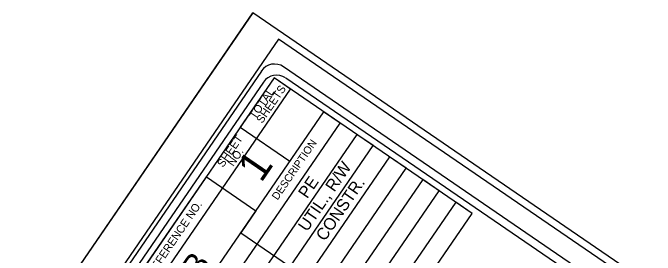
# Model space of a CAD drawing. Extents: x 2312641 to 2338852, y 590461 to 618614.
# Drawn here: x 2324050 to 2329669, y 616493 to 618614 of the extents above; entities that cross this region are included whole.
import ezdxf

# ---------------------------------------------------------------- set-up
doc = ezdxf.new("R2010")
doc.units = 0
for name, color, linetype in [('Exist Other Culture Sign Post Text', 7, 'Continuous'), ('Exist Property Iron Pin Cogo Number', 7, 'Continuous'), ('Exist Utilities Power Joint Use Telephone CELL', 7, 'Continuous'), ('Exist Utilities Power Joint Use Telephone Text', 7, 'Continuous'), ('Exist Vegetation Woods Line Text', 7, 'Continuous')]:
    doc.layers.add(name, color=color, linetype=linetype)

msp = doc.modelspace()

# ---------------------------------------------------------------- linework, layer by layer
at = {"layer": 'Exist Other Culture Sign Post Text'}
msp.add_line((2312821.5, 599166.9), (2326149.2, 618614.2), dxfattribs=at)
at = {"layer": 'Exist Property Iron Pin Cogo Number'}
for points in [[(2338313.5, 609989.2), (2326418.9, 618140.9)], [(2326224.4, 618104.7), (2314510.8, 601013.1)], [(2326242.4, 618007.3), (2315004.1, 601608.8)], [(2324303.9, 614770.3), (2326480.3, 617946.1), (2326336, 618045), (2324159.7, 614869.1)], [(2324456.3, 615302.3), (2325742.6, 617178.9), (2326175.5, 616882.1), (2326043.3, 616689.2), (2327342.5, 615798.9), (2328068.2, 616857.8), (2326336, 618045), (2326039.2, 617611.9), (2326472.3, 617315.3)], [(2336079.9, 611435.1), (2326436.9, 618043.7)], [(2324737.1, 614473.4), (2326913.5, 617649.2), (2326769, 617748.2), (2324592.6, 614572.4)], [(2325025.8, 614275.5), (2327202.1, 617451.4), (2327057.9, 617550.2), (2324881.4, 614374.5)], [(2325314.4, 614077.8), (2327490.8, 617253.6), (2327346.4, 617352.5), (2325170, 614176.7)], [(2325603.2, 613879.8), (2327779.7, 617055.6), (2327635.3, 617154.5), (2325458.9, 613978.9)], [(2325891.8, 613682.1), (2328068.2, 616857.8), (2327924, 616956.7), (2325747.4, 613781)]]:
    msp.add_lwpolyline(points, dxfattribs=at)
for centre in [(2326339.1, 618025.9), (2326357.3, 617928.6)]:
    msp.add_arc(centre, 140, 55.5761, 145.5761, dxfattribs=at)
at = {"layer": 'Exist Utilities Power Joint Use Telephone CELL'}
msp.add_lwpolyline([(2326149.2, 618614.2), (2312821.5, 599166.9), (2325524.4, 590461.2), (2338852.2, 609908.5)], close=True, dxfattribs=at)
at = {"layer": 'Exist Utilities Power Joint Use Telephone Text'}
msp.add_lwpolyline([(2325368.2, 590788.9), (2338557.5, 610034.1), (2326372.9, 618384.6), (2313183.6, 599139.4)], close=True, dxfattribs=at)

# ---------------------------------------------------------------- texts
at = {"layer": 'Exist Property Iron Pin Cogo Number'}
for s, height, p in [('SHEETS', 70, (2326231.5, 617641.2)), ('TOTAL', 70, (2326171.1, 617676.8)), ('SHEET', 70, (2325888.8, 617255.9)), ('DESCRIPTION', 67.2, (2326365.6, 616969.8)), ('NO.', 70, (2325978.6, 617264.8)), ('1', 270.9, (2326221.8, 617119.3)), ('STATE PROJECT REFERENCE NO.', 69.997, (2324827.7, 615652))]:
    msp.add_text(s, height=height, rotation=55.5761, dxfattribs=at).set_placement(p)
at = {"layer": 'Exist Vegetation Woods Line Text'}
for s, height, p in [('UTIL., R/W', 105, (2326624.1, 616692.1)), ('PE', 105, (2326625, 616981.7)), ('CONSTR.', 105, (2326779, 616608.6)), ('U-3609B', 210, (2325164.4, 615510.6))]:
    msp.add_text(s, height=height, rotation=55.5761, dxfattribs=at).set_placement(p)

doc.saveas('drawing.dxf')
